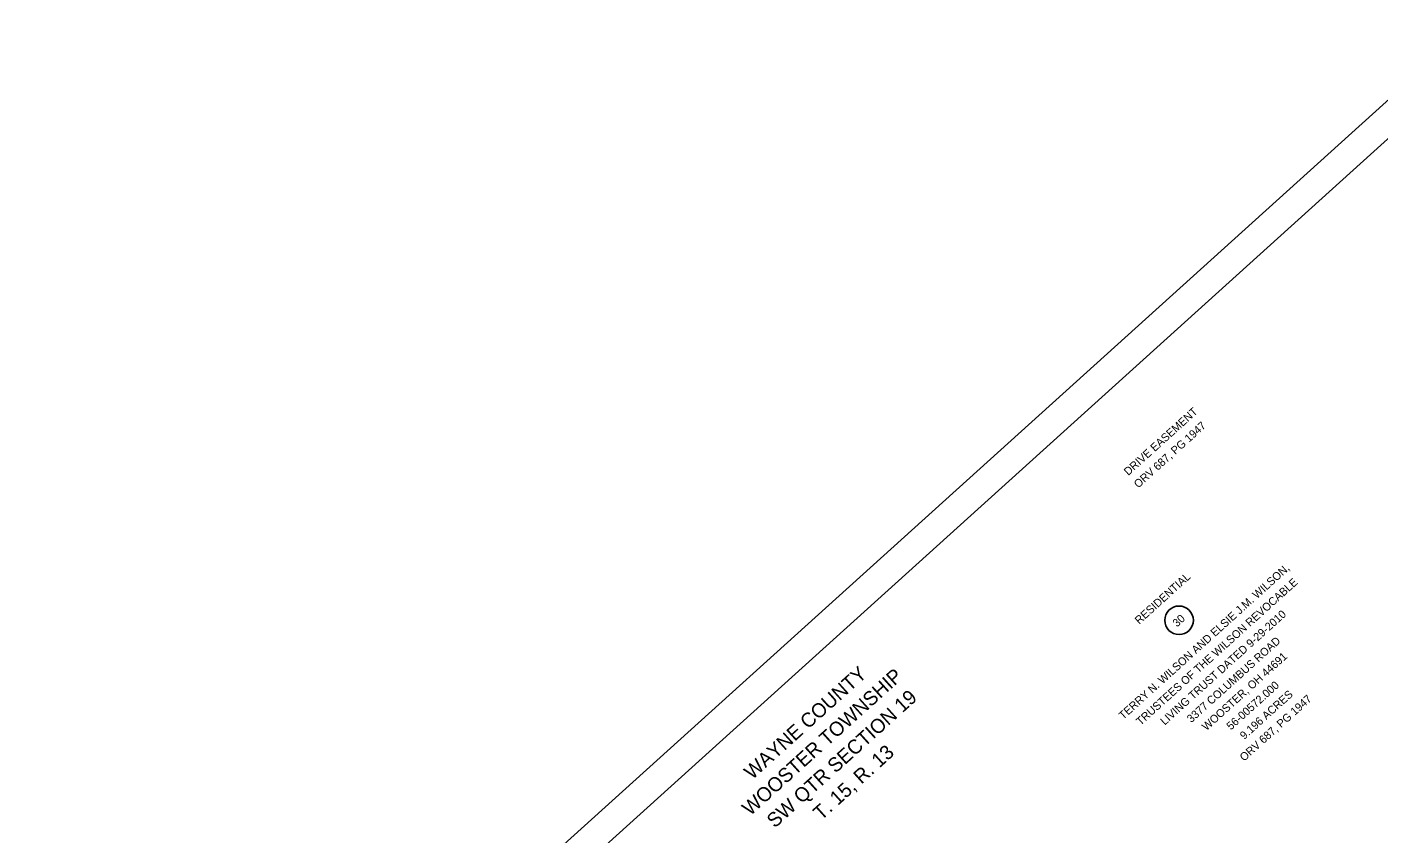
# Model space of a CAD drawing. Extents: x 138682 to 139482, y 476649 to 477431.
# Drawn here: x 138682.3 to 139155.4, y 477148.4 to 477430.8 of the extents above; entities that cross this region are included whole.
import ezdxf

# ---------------------------------------------------------------- set-up
doc = ezdxf.new("R2010")
doc.units = 0
for name, color, linetype in [('_CIVIL_CONSTRUCTION', 7, 'Continuous'), ('GE_X_Alignment', 7, 'Continuous'), ('GE_X_Alignment_100_Bearings', 7, 'Continuous'), ('GE_X_Alignment_100_Cardinal_Points', 7, 'Continuous')]:
    doc.layers.add(name, color=color, linetype=linetype)

msp = doc.modelspace()

# ---------------------------------------------------------------- linework, layer by layer
at = {"layer": '_CIVIL_CONSTRUCTION'}
msp.add_lwpolyline([(138977.21, 476648.51), (139481.8, 477104.35), (139186.84, 477430.85), (138682.25, 476975.01)], close=True, dxfattribs=at)
at = {"layer": 'GE_X_Alignment'}
msp.add_circle((139085.42, 477223.18), 5, dxfattribs=at)
at = {"layer": 'GE_X_Alignment_100_Cardinal_Points'}
msp.add_lwpolyline([(138711.22, 476987.7), (139186.13, 477416.72), (139467.67, 477105.07), (138992.77, 476676.04)], close=True, dxfattribs=at)

# ---------------------------------------------------------------- texts
at = {"layer": 'GE_X_Alignment'}
for s, p in [('DRIVE EASEMENT', (139067.65, 477273.68)), ('ORV 687, PG 1947', (139071.15, 477269.29)), ('TERRY N. WILSON AND ELSIE J.M. WILSON,', (139065.88, 477188.28)), ('RESIDENTIAL', (139071.47, 477221.63)), ('TRUSTEES OF THE WILSON REVOCABLE', (139071.95, 477186.22)), ('LIVING TRUST DATED 9-29-2010', (139080.4, 477186.31)), ('30', (139084.7, 477220.65)), ('3377 COLUMBUS ROAD', (139089.7, 477187.16)), ('WOOSTER, OH 44691', (139094.98, 477184.38)), ('56-00572.000', (139103.57, 477184.59)), ('9.196 ACRES', (139108.25, 477181.28)), ('ORV 687, PG 1947', (139108.18, 477173.67))]:
    msp.add_text(s, height=2.8, rotation=42.0943, dxfattribs=at).set_placement(p)
at = {"layer": 'GE_X_Alignment_100_Bearings'}
for s, p in [('               WAYNE COUNTY               ', (138915.34, 477148.51)), ('             WOOSTER TOWNSHIP             ', (138917.39, 477138.33)), ('             SW QTR SECTION 19            ', (138926.02, 477134.08)), ('               T. 15, R. 13               ', (138939.51, 477134.24))]:
    msp.add_text(s, height=5, rotation=42.0943, dxfattribs=at).set_placement(p)

doc.saveas('drawing.dxf')
